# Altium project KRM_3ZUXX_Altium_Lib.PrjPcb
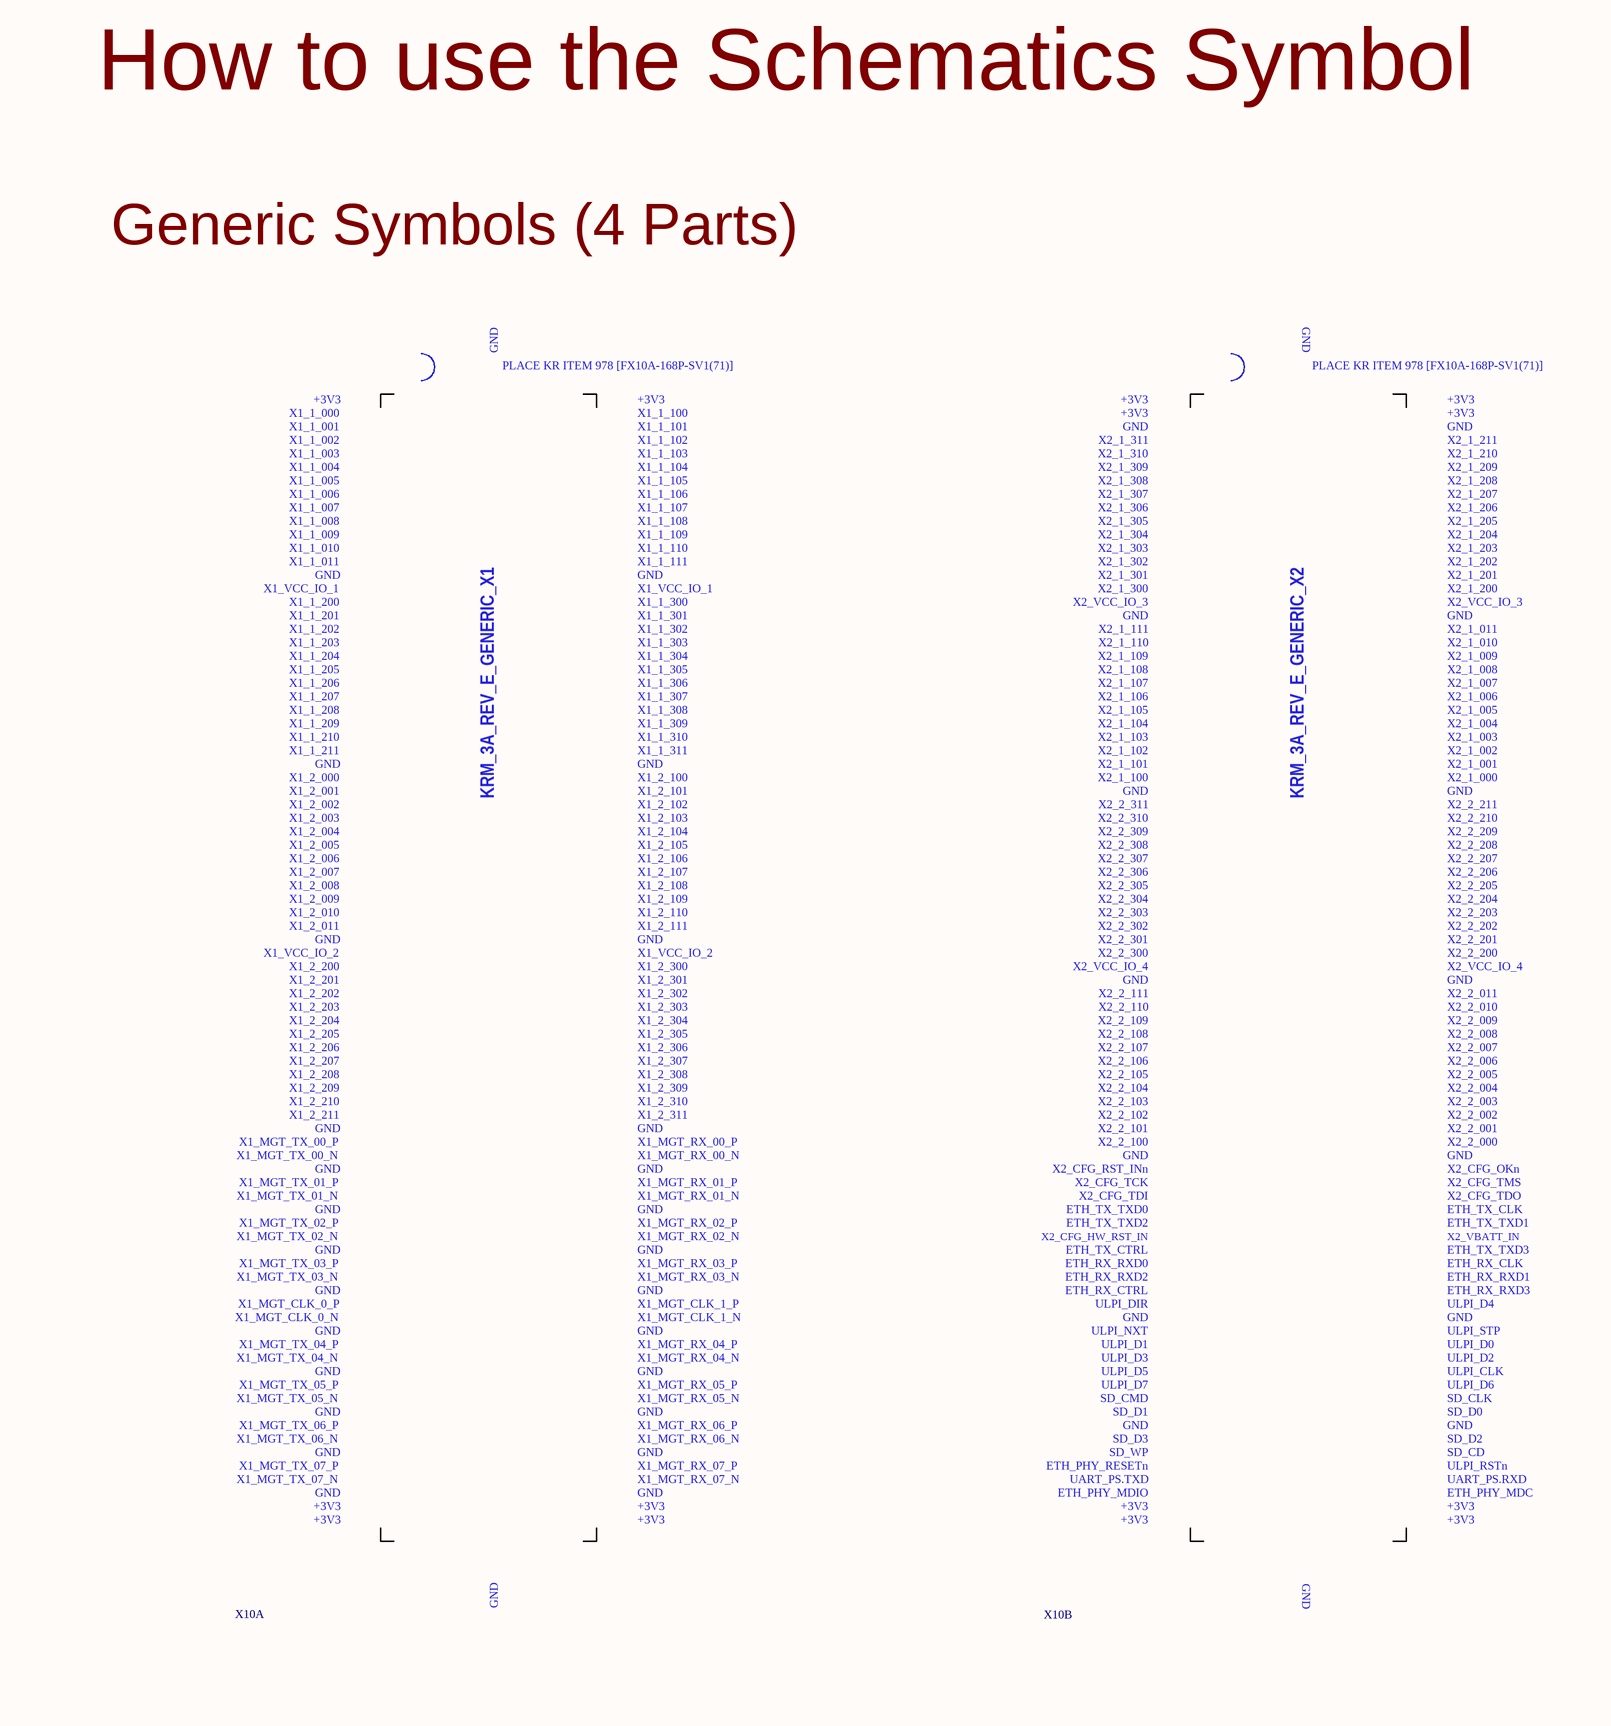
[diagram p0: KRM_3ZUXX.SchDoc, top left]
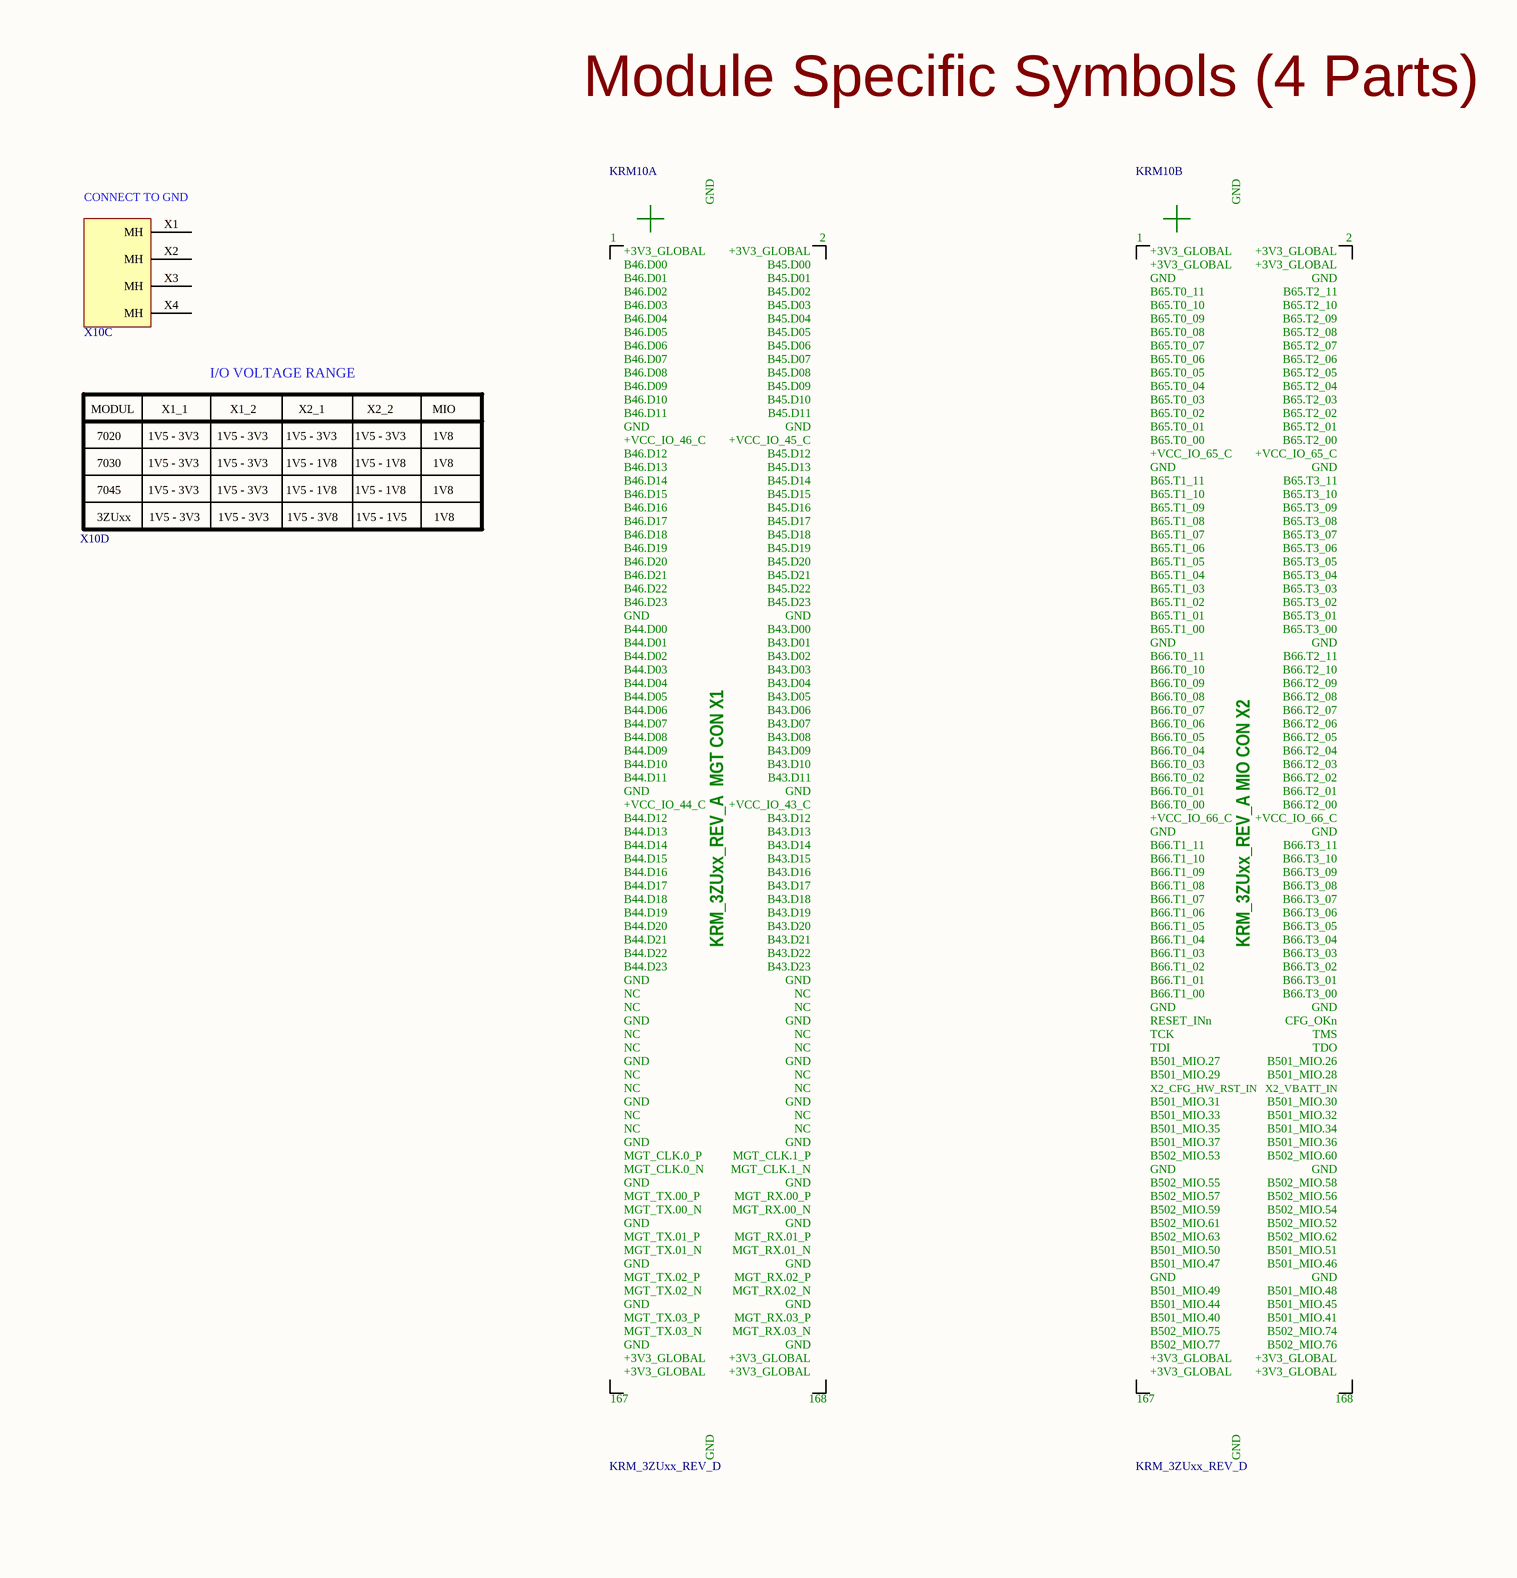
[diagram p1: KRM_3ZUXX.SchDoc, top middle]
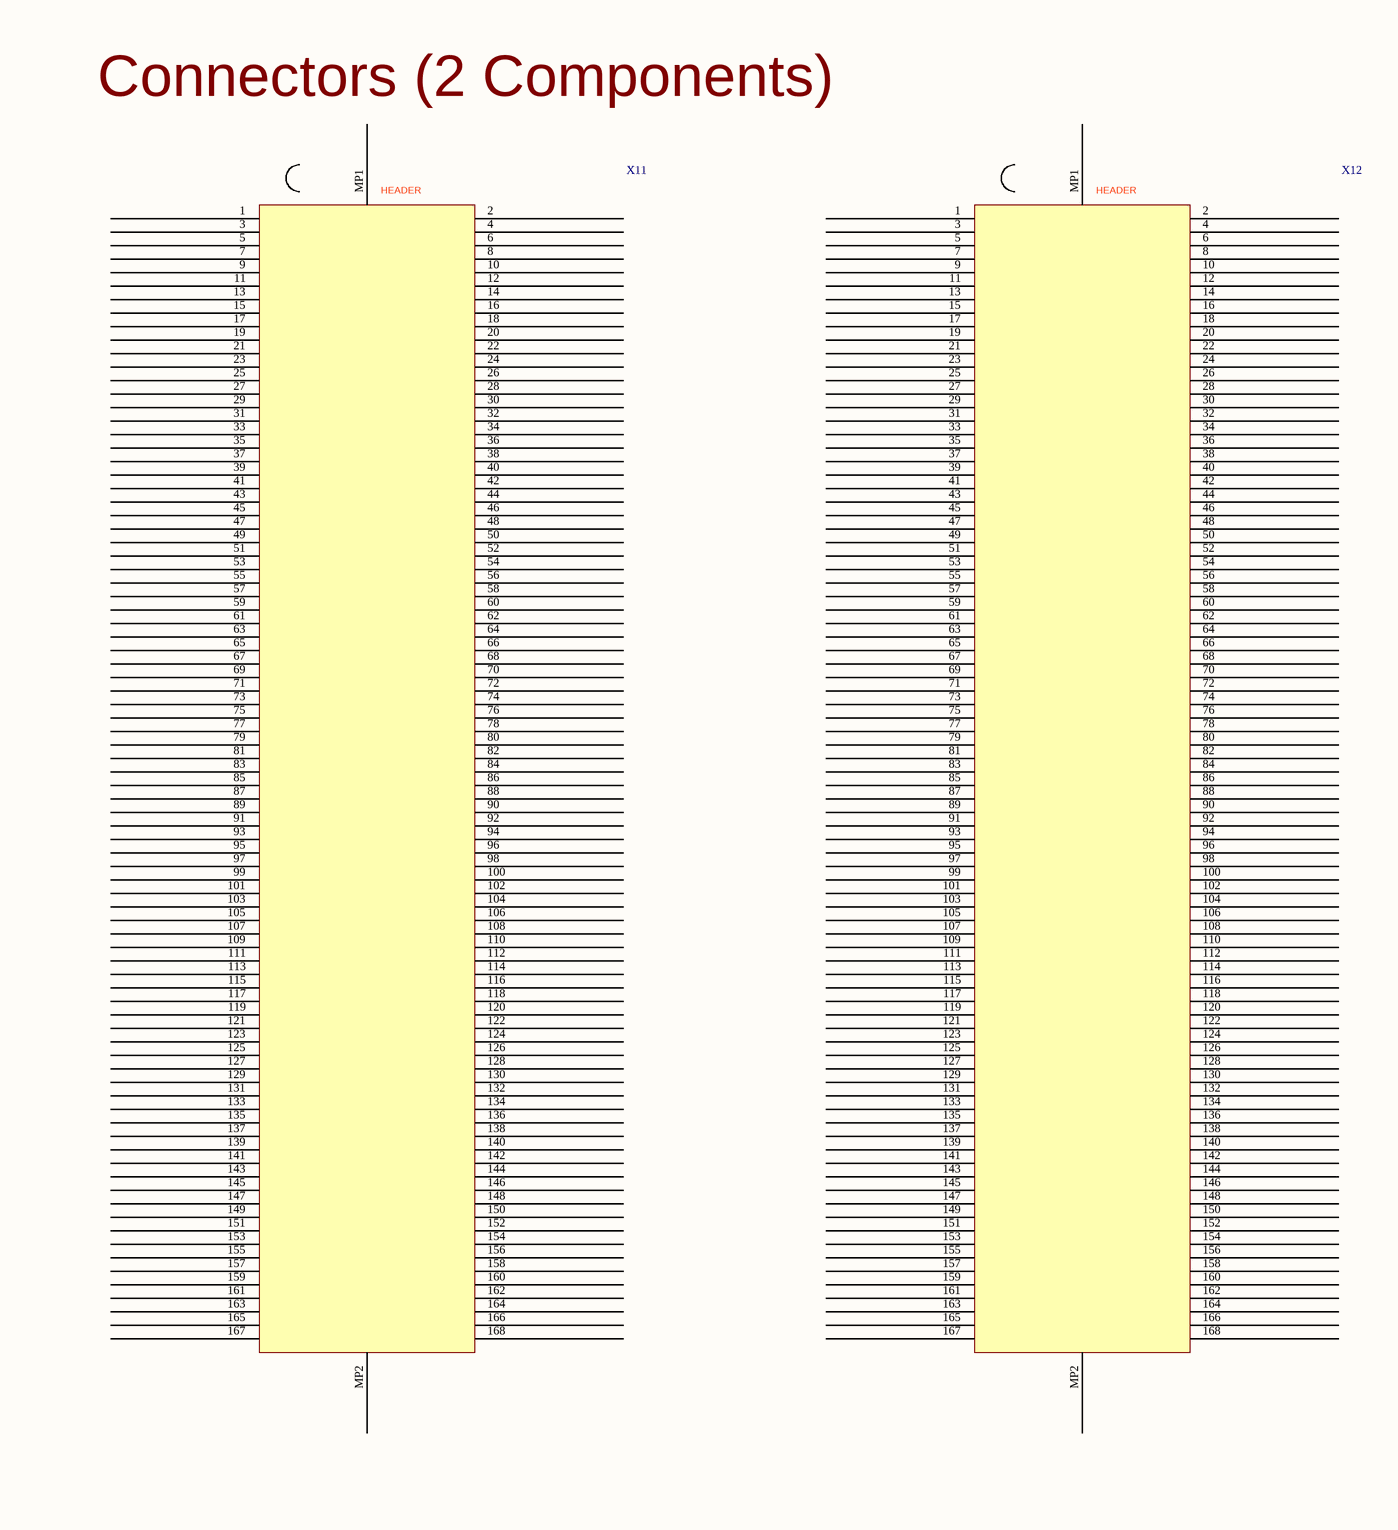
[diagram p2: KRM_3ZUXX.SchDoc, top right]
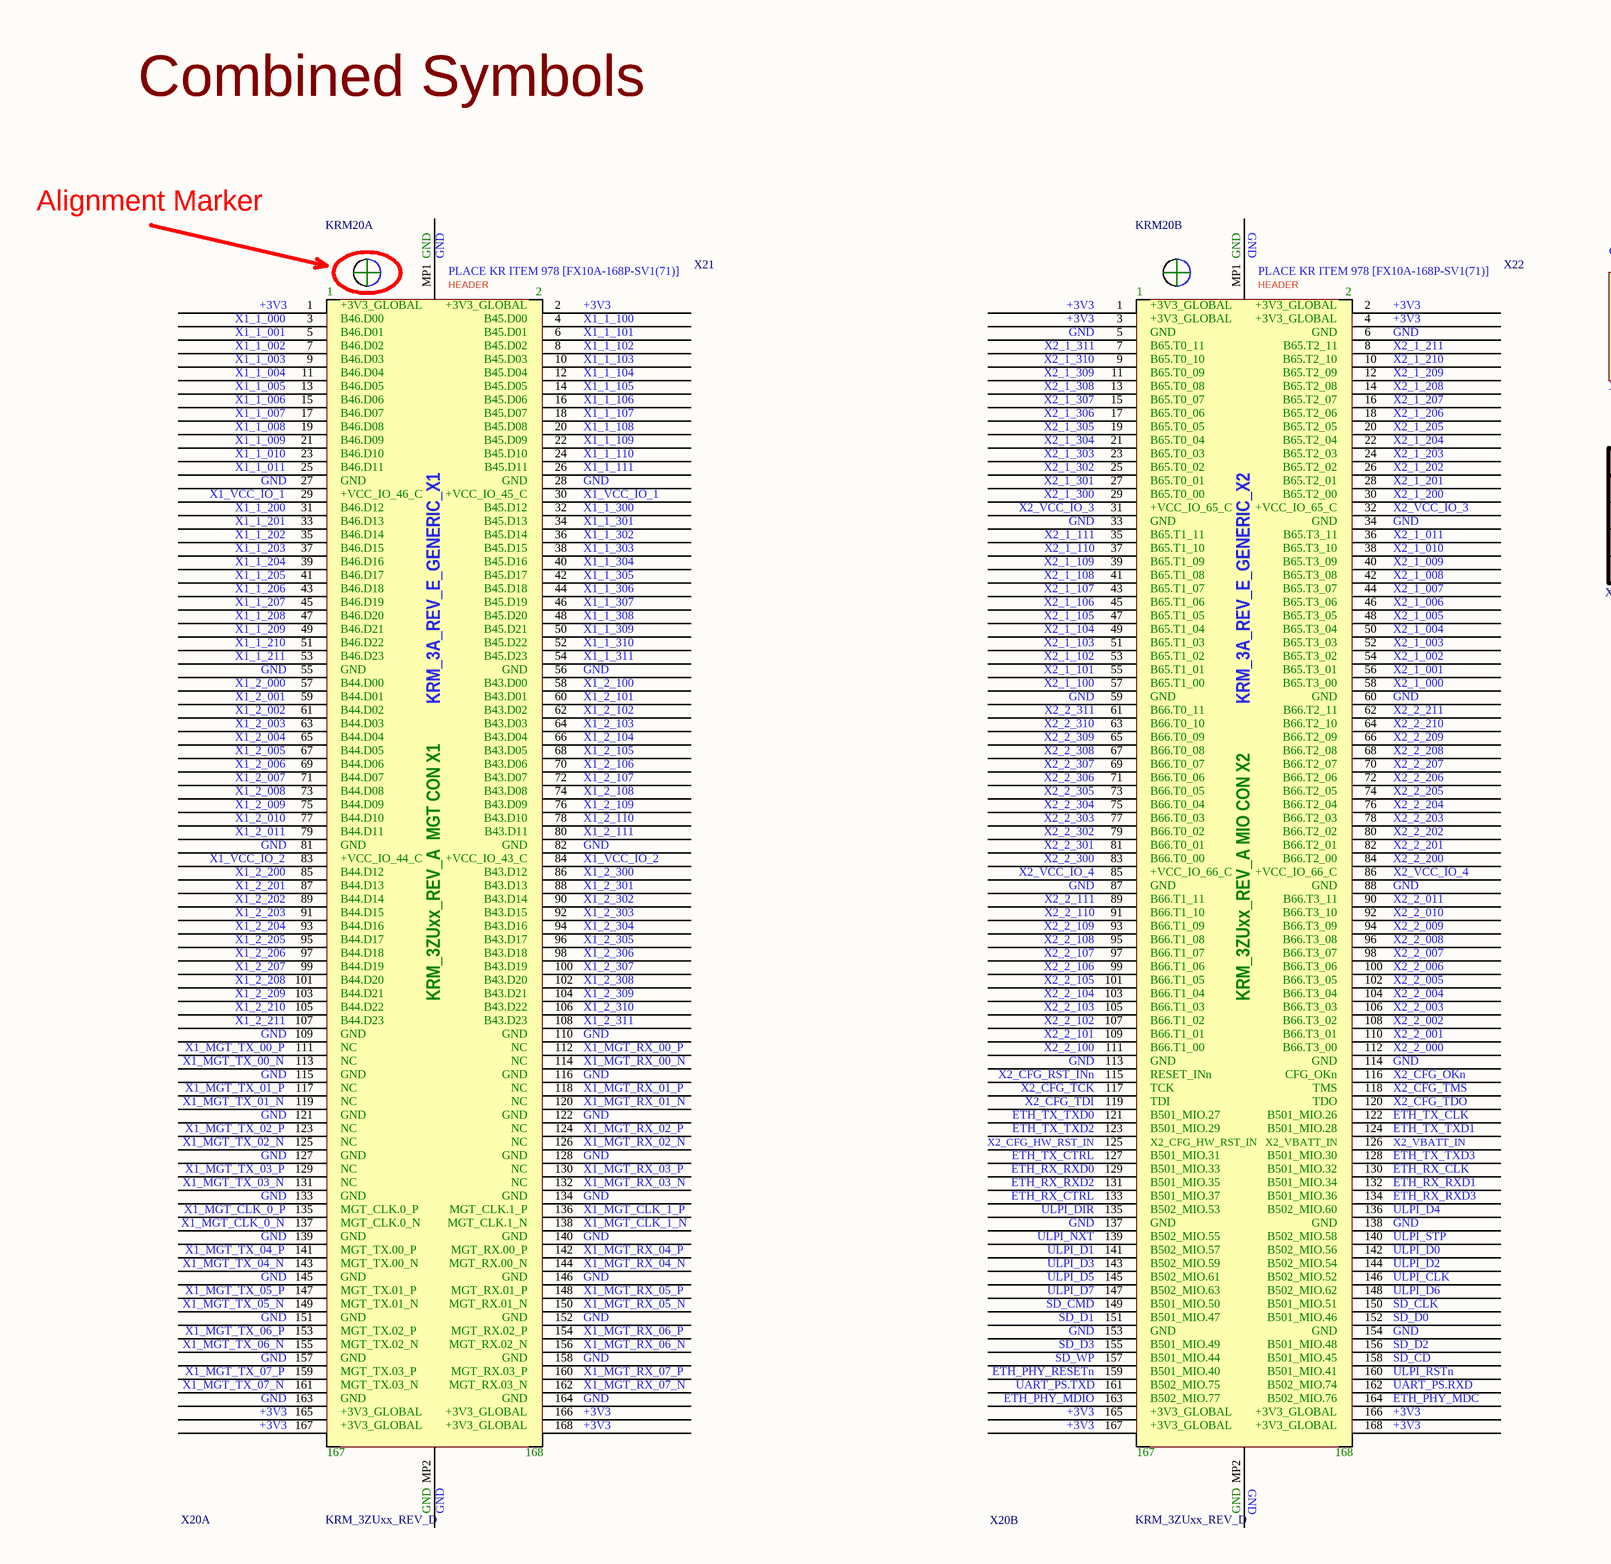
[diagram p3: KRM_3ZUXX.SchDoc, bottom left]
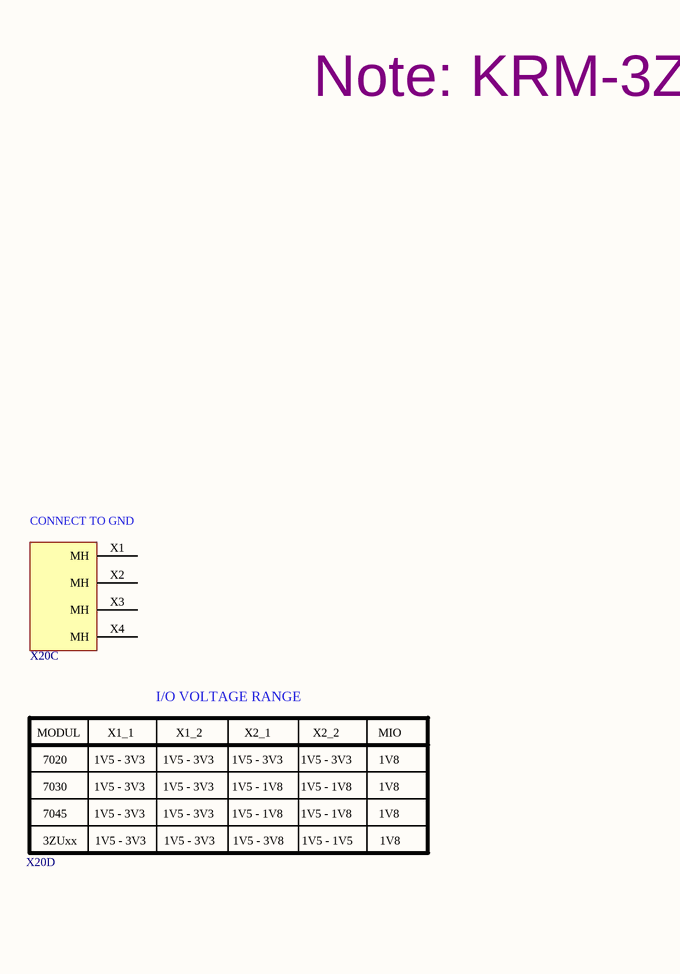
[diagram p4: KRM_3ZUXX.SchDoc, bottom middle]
Project_Title: KRM-3ZUXX Template Project
1 sheet, 8 parts. Net scope: global (net labels, ports and power ports of the same name join across sheets).
Board file: KRM_3ZUXX.PcbDoc

## Sheet KRM_3ZUXX.SchDoc: KRM-3ZUXX Module Symbols
size A0; ApprovedBy: _not used_; CheckedBy: _not used_; Author: KR/xx; CompanyName: _not used_; DrawnBy: _not used_; Engineer: _not used_; Organization: Knowledge Resources GmbH; Address1: Ackerstrasse 30; Address2: 4057 Basel, Switzerland; Address3: www.knowres.com; DocumentNumber: _tbd_; Revision: _not used_; SheetNumber: _tbd_; SheetTotal: _tbd_

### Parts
KRM10  KRM_3ZUxx_REV_D  [KRM_3ZUXX_REV_D]  (parts A,B of 2)
KRM20  KRM_3ZUxx_REV_D  [KRM_3ZUXX_REV_D]  (parts A,B of 2)
X10  KRM_3A_GENERIC_REV_E  [KRM_3A_GENERIC]  (value not drawn)  (parts A,B,C,D of 4)
X11  X_FX10A-168P-SV1(71)  [X_FX10A-168P-SV1(71)]  (value not drawn)
X12  X_FX10A-168P-SV1(71)  [X_FX10A-168P-SV1(71)]  (value not drawn)
X20  KRM_3A_GENERIC_REV_E  [KRM_3A_GENERIC]  (value not drawn)  (parts A,B,C,D of 4)
X21  X_FX10A-168P-SV1(71)  [X_FX10A-168P-SV1(71)]  (value not drawn)
X22  X_FX10A-168P-SV1(71)  [X_FX10A-168P-SV1(71)]  (value not drawn)

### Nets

Not connected (* = marked no-connect by the designer): X10 X1(MH) X2(MH) X3(MH) X4(MH); X11 1 2 3 4 5 6 7 8 9 10 11 12 13 14 15 16 17 18 19 20 21 22 23 24 25 26 27 28 29 30 31 32 33 34 35 36 37 38 39 40 41 42 43 44 45 46 47 48 49 50 51 52 53 54 55 56 57 58 59 60 61 62 63 64 65 66 67 68 69 70 71 72 73 74 75 76 77 78 79 80 81 82 83 84 85 86 87 88 89 90 91 92 93 94 95 96 97 98 99 100 101 102 103 104 105 106 107 108 109 110 111 112 113 114 115 116 117 118 119 120 121 122 123 124 125 126 127 128 129 130 131 132 133 134 135 136 137 138 139 140 141 142 143 144 145 146 147 148 149 150 151 152 153 154 155 156 157 158 159 160 161 162 163 164 165 166 167 168 MP1 MP2; X12 1 2 3 4 5 6 7 8 9 10 11 12 13 14 15 16 17 18 19 20 21 22 23 24 25 26 27 28 29 30 31 32 33 34 35 36 37 38 39 40 41 42 43 44 45 46 47 48 49 50 51 52 53 54 55 56 57 58 59 60 61 62 63 64 65 66 67 68 69 70 71 72 73 74 75 76 77 78 79 80 81 82 83 84 85 86 87 88 89 90 91 92 93 94 95 96 97 98 99 100 101 102 103 104 105 106 107 108 109 110 111 112 113 114 115 116 117 118 119 120 121 122 123 124 125 126 127 128 129 130 131 132 133 134 135 136 137 138 139 140 141 142 143 144 145 146 147 148 149 150 151 152 153 154 155 156 157 158 159 160 161 162 163 164 165 166 167 168 MP1 MP2; X20 X1(MH) X2(MH) X3(MH) X4(MH); X21 1 2 3 4 5 6 7 8 9 10 11 12 13 14 15 16 17 18 19 20 21 22 23 24 25 26 27 28 29 30 31 32 33 34 35 36 37 38 39 40 41 42 43 44 45 46 47 48 49 50 51 52 53 54 55 56 57 58 59 60 61 62 63 64 65 66 67 68 69 70 71 72 73 74 75 76 77 78 79 80 81 82 83 84 85 86 87 88 89 90 91 92 93 94 95 96 97 98 99 100 101 102 103 104 105 106 107 108 109 110 111 112 113 114 115 116 117 118 119 120 121 122 123 124 125 126 127 128 129 130 131 132 133 134 135 136 137 138 139 140 141 142 143 144 145 146 147 148 149 150 151 152 153 154 155 156 157 158 159 160 161 162 163 164 165 166 167 168 MP1 MP2; X22 1 2 3 4 5 6 7 8 9 10 11 12 13 14 15 16 17 18 19 20 21 22 23 24 25 26 27 28 29 30 31 32 33 34 35 36 37 38 39 40 41 42 43 44 45 46 47 48 49 50 51 52 53 54 55 56 57 58 59 60 61 62 63 64 65 66 67 68 69 70 71 72 73 74 75 76 77 78 79 80 81 82 83 84 85 86 87 88 89 90 91 92 93 94 95 96 97 98 99 100 101 102 103 104 105 106 107 108 109 110 111 112 113 114 115 116 117 118 119 120 121 122 123 124 125 126 127 128 129 130 131 132 133 134 135 136 137 138 139 140 141 142 143 144 145 146 147 148 149 150 151 152 153 154 155 156 157 158 159 160 161 162 163 164 165 166 167 168 MP1 MP2

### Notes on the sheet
- How to use the Schematics Symbol
- Generic Symbols (4 Parts)
- Module Specific Symbols (4 Parts)
- Connectors (2 Components)
- Note: KRM-3ZUXX Rev.A to Rev.D have identical electrical interfaces.
- Combined Symbols
- Alignment Marker

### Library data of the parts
KRM10 KRM20 = KRM_3ZUxx_REV_D: COM/FPGA MODULE with 3ZUxx FPGAs
X10 X20 = KRM_3A_GENERIC_REV_E: 168 PIN HEADER ASSIGNMENT
X11 X12 X21 X22 = X_FX10A-168P-SV1(71): 168 PIN HEADER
